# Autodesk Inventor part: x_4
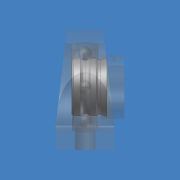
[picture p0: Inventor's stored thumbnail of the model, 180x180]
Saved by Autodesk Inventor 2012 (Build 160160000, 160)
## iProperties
Company: CAD-Verlag
Part Number: x_4
Document SubType Name: Modeling
Created: 2004-09
Material: Standard
Designer: Greiling
Manufacturer: Standard
Standards Organization: Custom
Density: 1 g/cm^3
Control State: 0
Master: False
Checked Out: False
Shininess: 64.0
Length Units: 11269
Angle Units: 11279
Time Units: 11290
Mass Units: 11283
Length Display Precision: 3
Angle Display Precision: 2
Compacted: True
Übersetzungsnorm: STEP AP214CD
Dateiname: w2c22665.stp
Vorprozessor: ACIS
Postprozessor: Build: 081d, Release: 8 SP1 - Date: Tue 01/26/2004
Gesendete Einheiten: MILLIMETERS
Unbestimmtheit: 1e-06
Density: 0.0
Volumn: 0.0
Area: 0.0
PropertySet Name: Model Information
Author: Jürgen Kronas
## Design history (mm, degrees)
feature "Basis1"
node "Volumenkörper1"
node "Volumenkörpern"
node "Oberflächenkörpern"
